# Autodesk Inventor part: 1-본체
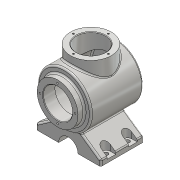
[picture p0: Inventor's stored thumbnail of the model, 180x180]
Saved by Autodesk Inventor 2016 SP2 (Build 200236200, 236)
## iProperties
Created: 2017-04
Part Number: 1-본체
Material: 알루미늄 6061
Document SubType Name: Modeling
Designer: H
Density: 2.7 g/cm^3
Appearance: 알루미늄 - 평지
Mass: 1664.44 g
Surface Area: 1066.89 cm^2
Volume: 616.46 cm^3
Author: H
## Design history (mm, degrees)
sketch "스케치2"
  geometry: L1 (-50, 0)-(-62, 0); L2 (-62, 0)-(-62, 38); L3 (-62, 38)-(-50, 38); L4 (-50, 38)-(-50, 0); L5 (-50, 0)-(46.336, 0); L6 (46.336, 0)-(46.336, 50); L7 (46.336, 50)-(-50, 50); L8 (-50, 50)-(-50, 0); L9 (46.336, 0)-(58, 0); A1 r 113 centre (-55, 0) between (58, 0) and (46.336, 50); 1 further point
  constraints: 18 end point, 4 parallel, 3 horizontal, 3 point on line, 2 perpendicular, 2 point on circle, 1 centre point
  dimensions: "d0" = 108 distance from line of L8 L9.end; "d1" = 12 distance of L2.end L3.end; "d2" = 76 diameter of L3 L1; "d3" = 100 diameter of L7 L5; "d4" = 113 radius of A1; "d5" = 50 distance from line of L4 point (0, 0)
revolve "회전1" sketch "스케치2" stored, may be unused: angle "d6" = 90 deg
sketch "스케치3"
  geometry: C1 r 38 at (0, 0); 1 further point
  constraints: 1 centre point, 1 coincident
  dimensions: "d7" = 76 diameter of C1
extrude "돌출1" join sketch "스케치3" distance "d8" = 65; taper "d9" = 0 deg
feature "쉘1" dims "d28" = 11, "d29" = 11, "d30" = 10
sketch "스케치7"
  geometry: L1 (-50, -50)-(-50, 50) reference; L2 (38, -82)-(-42, -82); L3 (-42, -82)-(-42, -72); L4 (-42, -72)-(38, -72); L5 (38, -72)-(38, -82); L6 (38, 65)-(-38, 65) reference; 1 further point
  constraints: 8 end point, 2 parallel, 1 horizontal, 1 perpendicular
  dimensions: "d12" = 8 distance between parallel lines of L1 L3; "d13" = 80 distance of L2.start L2.end; "d14" = 10 distance of L4.end L2.start; "d15" = 147 distance between parallel lines of L2 L6
extrude "돌출2" join sketch "스케치7" stored distance "d16" = 120; taper "d17" = 0 deg
sketch "스케치11"
  geometry: L1 (0, 10)-(38.416, 36.899); L2 (38.416, 36.899)-(81.584, 36.899); L3 (81.584, 36.899)-(120, 10); L4 (120, 10)-(0, 10); L5 (0, 0)-(0, 10) reference; A1 r 50 centre (60, 82) between (81.584, 36.899) and (38.416, 36.899) reference; 3 further points
  constraints: 8 end point, 2 coincident, 2 point on circle, 1 horizontal, 1 parallel
  dimensions: "d34" = 55 deg angle of L5 L1
extrude "돌출4" join sketch "스케치11" distance "d23" = 80; taper "d24" = 0 deg
node "작업 평면2"
sketch "스케치12"
  geometry: L1 (0, 0)-(120, 0) reference; C1 r 18 at (60, 0); 1 further point
  constraints: 1 centre point, 1 midpoint, 1 vertical alignment
  dimensions: "d25" = 18 radius of C1
extrude "돌출5" cut sketch "스케치12" stored distance "d26" = 80; taper "d27" = 0 deg
sketch "스케치15"
  geometry: 2 further points
  constraints: 1 coincident, 1 other
feature "엠보싱1" sketch "스케치15" dims "d0" = 108, "d1" = 12, "d2" = 76, "d3" = 100, "d4" = 113, "d5" = 50, "d12" = 8, "d13" = 80, "d14" = 10, "d15" = 147, "d31" = 0.5, "d32" = 0
sketch "스케치16"
  geometry: L1 (0, 0)-(0, 32.5)
  constraints: 2 end point, 1 vertical
  dimensions: "d35" = 32.5 distance of L1.start L1.end
hole "구멍1" sketch "스케치16" at (0, 32.5) diameter "d36" = 3.242; stored, may be unused: countersink angle "d40" = 90 deg, drill point angle "d42" = 118 deg; dims "d37" = 8, "d38" = 4, "d39" = 2, "d41" = 10
sketch "스케치17"
  geometry: L1 (0, 0)-(0, 32.5)
  constraints: 2 end point, 1 vertical
  dimensions: "d46" = 32.5 distance of L1.start L1.end
hole "구멍2" sketch "스케치17" at (0, 32.5) diameter "d47" = 3.242; stored, may be unused: countersink angle "d51" = 90 deg, drill point angle "d53" = 118 deg; dims "d48" = 8, "d49" = 4, "d50" = 2, "d52" = 10
node "작업 평면4"
sketch "스케치22"
  geometry: L1 (-60, -14)-(-50, -14); L2 (-50, -30)-(-60, -30); L3 (-60, -30)-(-60, -14); L4 (-60, -42)-(-60, 38) reference; L5 (-21.584, -42)-(-60, -42) reference; A1 r 8 centre (-50, -22) between (-50, -30) and (-50, -14); 1 further point
  constraints: 6 end point, 2 point on circle, 2 tangent, 1 centre point, 1 collinear, 1 horizontal, 1 parallel
  dimensions: "d80" = 20 distance from line of L5 A1.centre; "d81" = 10 distance from line of A1.centre L3; "d82" = 16 distance of L2.end L1.start
extrude "돌출7" cut sketch "스케치22" distance "d83" = 26; taper "d84" = 0 deg
hole "구멍4" diameter "d87" = 8; stored, may be unused: countersink angle "d91" = 90 deg, drill point angle "d93" = 118 deg; dims "d85" = 10, "d86" = 10, "d88" = 8, "d89" = 4, "d90" = 2, "d92" = 10
sketch "스케치23"
  geometry: L1 (-50, -22)-(50, -22); L2 (50, -22)-(50, 18); L3 (50, 18)-(-50, 18); L4 (-50, 18)-(-50, -22); C1 r 4 at (-50, -22) reference; 1 further point
  constraints: 8 end point, 2 parallel, 1 horizontal, 1 perpendicular
  dimensions: "d94" = 40 distance of L1.end L2.end; "d95" = 100 distance of L2.end L3.end
sketch "스케치24"
  geometry: L1 (-50, -22)-(-50, 18); C1 r 4 at (-50, -22) reference; 1 further point
  constraints: 2 end point, 1 vertical
  dimensions: "d102" = 40 distance of L1.start L1.end
fillet "모깎기1" dims "d106" = 3
chamfer "모따기1" distance "d107" = 1; stored, may be unused: second distance "d108" = 2, angle "d109" = 55 deg
fillet "모깎기2" dims "d110" = 3
fillet "모깎기3" dims "d111" = 3
fillet "모깎기4" dims "d112" = 3
fillet "모깎기5" dims "d113" = 3
fillet "모깎기6" dims "d114" = 3
fillet "모깎기7" dims "d115" = 3
node "솔리드1"
pattern_circular "원형 패턴1" dims angle "d44" = 360 deg
pattern_circular "원형 패턴2" dims angle "d55" = 360 deg
pattern_linear "직사각형 패턴2"
mirror "대칭1"
